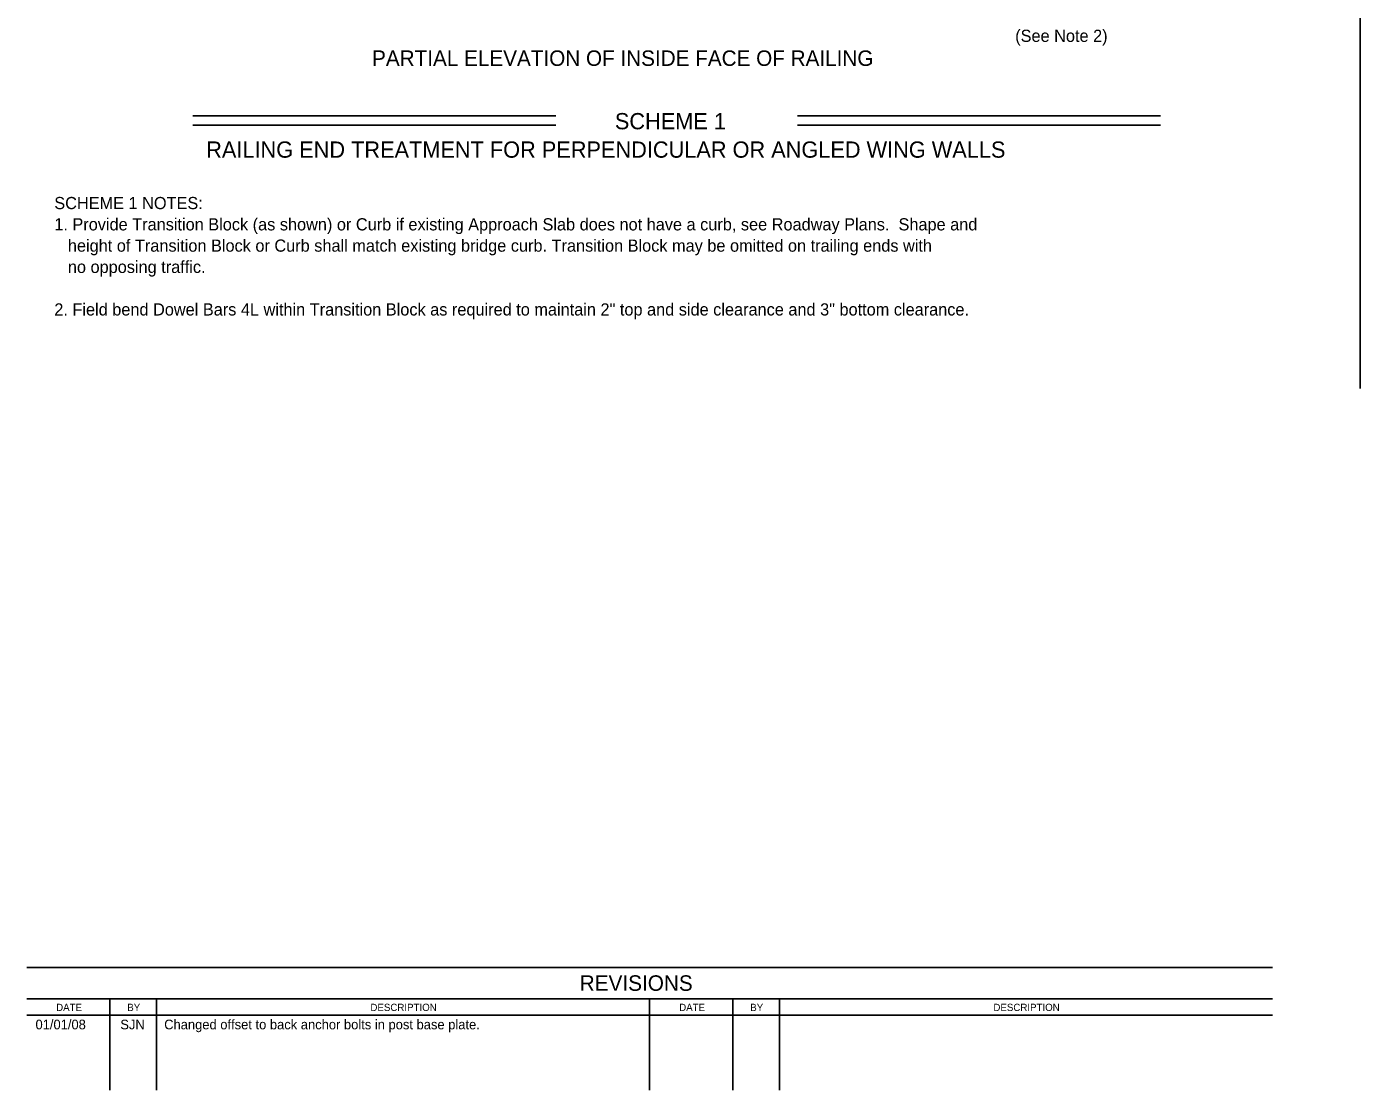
# Model space of a CAD drawing. Extents: x 21665 to 21741.5, y 56121.9 to 56164.2.
# Drawn here: x 21672.11 to 21694.17, y 56121.86 to 56139.46 of the extents above; entities that cross this region are included whole.
import ezdxf

# ---------------------------------------------------------------- set-up
doc = ezdxf.new("R2010")
doc.units = 0
for name, color, linetype in [('Border', 7, 'Continuous'), ('Dimension', 7, 'Continuous'), ('TextStructures', 7, 'Continuous')]:
    doc.layers.add(name, color=color, linetype=linetype)

msp = doc.modelspace()

# ---------------------------------------------------------------- linework, layer by layer
at = {"layer": 'Border'}
for p, q in [((21694.168, 56159.403), (21694.168, 56133.475)), ((21692.718, 56123.893), (21672.106, 56123.893)), ((21692.718, 56123.378), (21672.106, 56123.378)), ((21673.483, 56123.378), (21673.483, 56121.863)), ((21674.256, 56123.378), (21674.256, 56121.863)), ((21682.412, 56123.378), (21682.412, 56121.863)), ((21683.789, 56123.378), (21683.789, 56121.863)), ((21684.562, 56123.378), (21684.562, 56121.863)), ((21672.106, 56123.105), (21692.718, 56123.105))]:
    msp.add_line(p, q, dxfattribs=at)
at = {"layer": 'Dimension'}
for p, q in [((21674.857, 56137.988), (21680.86, 56137.988)), ((21674.857, 56137.831), (21680.86, 56137.831)), ((21684.86, 56137.988), (21690.86, 56137.988)), ((21684.86, 56137.831), (21690.86, 56137.831))]:
    msp.add_line(p, q, dxfattribs=at)

# ---------------------------------------------------------------- texts
for s, height, p in [('(See Note 2)', 0.2016, (21688.459, 56139.209)), ('SCHEME 1', 0.2688, (21681.836, 56137.763)), ('RAILING END TREATMENT FOR PERPENDICULAR OR ANGLED WING WALLS', 0.2688, (21675.076, 56137.293)), ('SCHEME 1 NOTES:', 0.2016, (21672.563, 56136.442)), ('1. Provide Transition Block (as shown) or Curb if existing Approach Slab does not have a curb, see Roadway Plans.  Shape and ', 0.2016, (21672.563, 56136.09)), ('   height of Transition Block or Curb shall match existing bridge curb. Transition Block may be omitted on trailing ends with ', 0.2016, (21672.563, 56135.738)), ('   no opposing traffic.', 0.2016, (21672.563, 56135.386)), ('2. Field bend Dowel Bars 4L within Transition Block as required to maintain 2" top and side clearance and 3" bottom clearance.   ', 0.2016, (21672.563, 56134.682))]:
    msp.add_text(s, height=height, dxfattribs=at).set_placement(p)
at = {"layer": 'TextStructures'}
for s, height, p in [('PARTIAL ELEVATION OF INSIDE FACE OF RAILING', 0.256, (21677.82, 56138.812)), ('REVISIONS', 0.2567, (21681.255, 56123.509)), ('BY', 0.1201, (21673.77, 56123.175)), ('BY', 0.1201, (21684.076, 56123.175)), ('01/01/08', 0.16, (21672.252, 56122.872)), ('SJN', 0.16, (21673.655, 56122.872)), ('Changed offset to back anchor bolts in post base plate.', 0.16, (21674.381, 56122.872))]:
    msp.add_text(s, height=height, dxfattribs=at).set_placement(p)
for s, height, rotation, p in [('DATE', 0.1196, 359.8693, (21672.594, 56123.176)), ('DESCRIPTION', 0.12007, 0.0498, (21677.792, 56123.175)), ('DATE', 0.1196, 359.8693, (21682.901, 56123.176)), ('DESCRIPTION', 0.12007, 0.0498, (21688.098, 56123.175))]:
    msp.add_text(s, height=height, rotation=rotation, dxfattribs=at).set_placement(p)

doc.saveas('drawing.dxf')
